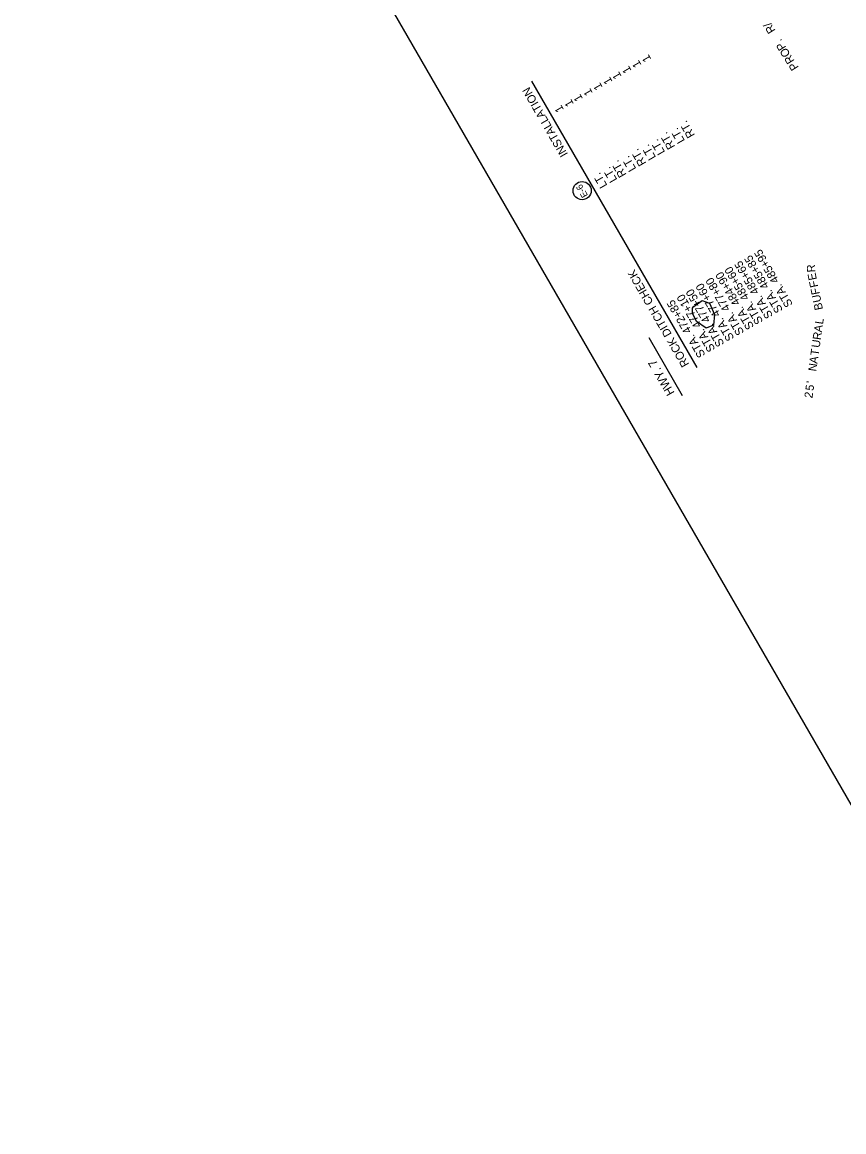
# Model space of a CAD drawing. Extents: x 956270 to 957915, y 1920520 to 1922423.
# Drawn here: x 956270 to 956869, y 1920520 to 1921329 of the extents above; entities that cross this region are included whole.
import ezdxf

# ---------------------------------------------------------------- set-up
doc = ezdxf.new("R2010")
doc.units = 0
for name, color, linetype in [('1', 7, 'Continuous'), ('44', 7, 'Continuous'), ('NO PLOT', 7, 'Continuous'), ('R_Draft', 7, 'Continuous'), ('S_TREE', 7, 'Continuous')]:
    doc.layers.add(name, color=color, linetype=linetype)

msp = doc.modelspace()

# ---------------------------------------------------------------- linework, layer by layer
at = {"layer": '1'}
msp.add_circle((956678.51, 1921206.5), 6.61, dxfattribs=at)
at = {"layer": '44'}
for p, q in [((956762.39, 1921077.68), (956641.89, 1921286.4)), ((956751.76, 1921056.9), (956727.34, 1921099.2)), ((956751.76, 1921056.9), (956727.34, 1921099.2))]:
    msp.add_line(p, q, dxfattribs=at)
at = {"layer": 'NO PLOT'}
msp.add_lwpolyline([(957012.51, 1920520.44), (956420.48, 1921545.87), (956463.26, 1921570.57), (956365.36, 1921740.14), (956378, 1921747.44), (956270.25, 1921934.07), (956666.17, 1922162.65), (956816.66, 1921901.98), (956749.98, 1921863.48), (956962.48, 1921495.42), (957029.16, 1921533.92), (957172.25, 1921286.08), (957120.9, 1921256.43), (957292.23, 1920959.68), (957343.58, 1920989.33), (957463.85, 1920781.02)], close=True, dxfattribs=at)
msp.add_lwpolyline([(957012.51, 1920520.44), (956420.48, 1921545.87), (956463.26, 1921570.57), (956365.36, 1921740.14), (956378, 1921747.44), (956270.25, 1921934.07), (956666.17, 1922162.65), (956816.66, 1921901.98), (956749.98, 1921863.48), (956962.48, 1921495.42), (957029.16, 1921533.92), (957172.25, 1921286.08), (957120.9, 1921256.43), (957292.23, 1920959.68), (957343.58, 1920989.33), (957463.85, 1920781.02)], close=True, dxfattribs=at)
msp.add_lwpolyline([(957012.51, 1920520.44), (956420.48, 1921545.87), (956463.26, 1921570.57), (956365.36, 1921740.14), (956378, 1921747.44), (956270.25, 1921934.07), (956666.17, 1922162.65), (956816.66, 1921901.98), (956749.98, 1921863.48), (956962.48, 1921495.42), (957029.16, 1921533.92), (957172.25, 1921286.08), (957120.9, 1921256.43), (957292.23, 1920959.68), (957343.58, 1920989.33), (957463.85, 1920781.02)], close=True, dxfattribs=at)
msp.add_lwpolyline([(957012.51, 1920520.44), (956420.48, 1921545.87), (956463.26, 1921570.57), (956365.36, 1921740.14), (956378, 1921747.44), (956270.25, 1921934.07), (956666.17, 1922162.65), (956816.66, 1921901.98), (956749.98, 1921863.48), (956962.48, 1921495.42), (957029.16, 1921533.92), (957172.25, 1921286.08), (957120.9, 1921256.43), (957292.23, 1920959.68), (957343.58, 1920989.33), (957463.85, 1920781.02)], close=True, dxfattribs=at)
at = {"layer": 'S_TREE'}
msp.add_lwpolyline([(956759.27, 1921121.6), (956766.02, 1921126.33), (956771.25, 1921124.48), (956774.9, 1921116.16), (956774.28, 1921108.55), (956768.88, 1921106.31), (956761.87, 1921111.05), (956758.92, 1921117.07), (956758.89, 1921120.78), (956759.85, 1921122.19)], dxfattribs=at)

# ---------------------------------------------------------------- texts
at = {"layer": '1'}
msp.add_text('E-6 ', height=4.8, rotation=120, dxfattribs=at).set_placement((956682.92, 1921203.05))
at = {"layer": '44'}
for s, height, p in [('1', 6, (956721.89, 1921298.17)), ('1', 6, (956729.07, 1921302.32)), ('1', 6, (956707.46, 1921289.84)), ('1', 6, (956714.68, 1921294.01)), ('1', 6, (956693.64, 1921281.86)), ('1', 6, (956700.82, 1921286.01)), ('INSTALLATION', 6, (956668.31, 1921233.12)), ('1', 6, (956679.21, 1921273.53)), ('1', 6, (956686.43, 1921277.7)), ('1', 6, (956665.39, 1921265.55)), ('1', 6, (956672.61, 1921269.72)), ('LT.', 6, (956753.6, 1921242.93)), ('RT.', 6, (956760.88, 1921246.97)), ('RT.', 6, (956746.45, 1921238.64)), ('RT.', 6, (956725.42, 1921226.5)), ('LT.', 6, (956732.56, 1921230.79)), ('LT.', 6, (956739.17, 1921234.6)), ('RT.', 6, (956710.99, 1921218.17)), ('LT.', 6, (956718.13, 1921222.45)), ('LT.', 6, (956704.31, 1921214.48)), ('LT.', 6, (956697.1, 1921210.31)), ('STA. 485+95', 6, (956832.3, 1921123.58)), ('STA. 485+65', 6, (956817.86, 1921115.25)), ('STA. 485+85', 6, (956825.08, 1921119.41)), ('ROCK DITCH CHECK', 6, (956756.74, 1921079.96)), ('STA. 485+60', 6, (956810.65, 1921111.08)), ('STA. 477+80', 6, (956796.83, 1921103.1)), ('STA. 484+90', 6, (956804.05, 1921107.27)), ('STA. 477+50', 6, (956782.4, 1921094.77)), ('STA. 477+60', 6, (956789.62, 1921098.94)), ('STA. 472+85', 6, (956768.58, 1921086.79)), ('STA. 477+10', 6, (956775.8, 1921090.96)), ('HWY. 7', 6.25, (956746.07, 1921059.21)), ('HWY. 7', 6.25, (956746.07, 1921059.21))]:
    msp.add_text(s, height=height, rotation=120, dxfattribs=at).set_placement(p)
at = {"layer": 'R_Draft'}
for s, rotation, p in [('/', 122.05288, (956816.71, 1921328.09)), ('R', 122.05288, (956819.72, 1921323.28)), ('.', 122.05288, (956824.46, 1921315.71)), ('P', 122.05288, (956827.46, 1921310.91)), ('O', 122.05288, (956830.57, 1921305.94)), ('R', 122.05288, (956833.58, 1921301.14)), ('P', 122.05288, (956836.59, 1921296.33)), ('R', 92.10778, (956848.49, 1921147.03)), ('E', 101.55546, (956849.68, 1921141.77)), ('F', 101.55546, (956850.76, 1921136.49)), ('F', 101.55546, (956851.84, 1921131.22)), ('U', 101.55546, (956852.99, 1921125.57)), ('B', 101.55546, (956854.13, 1921120.02)), ('A', 81.81509, (956853.27, 1921102.99)), ('L', 81.81509, (956854.11, 1921108.79)), ('R', 81.81509, (956852.46, 1921097.38)), ('T', 81.81509, (956850.81, 1921085.88)), ('U', 81.81509, (956851.64, 1921091.68)), ('A', 81.81509, (956849.98, 1921080.08)), ('N', 81.81509, (956849.17, 1921074.47)), ("'", 81.81509, (956847.9, 1921065.63)), ('2', 81.81509, (956846.36, 1921054.97)), ('5', 81.81509, (956847.13, 1921060.3))]:
    msp.add_text(s, height=6, rotation=rotation, dxfattribs=at).set_placement(p)

doc.saveas('drawing.dxf')
